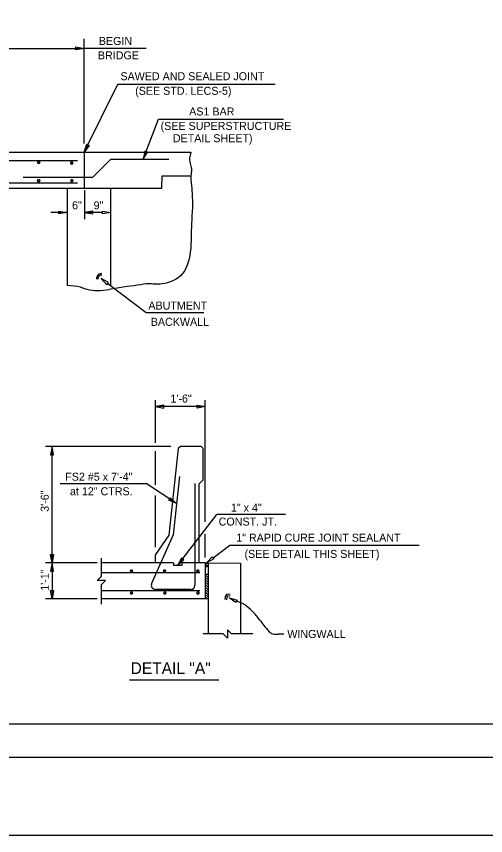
# Model space of a CAD drawing. Extents: x 570 to 2152770, y 726 to 141756.
# Drawn here: x 2151329.5 to 2151386, y 141477.7 to 141576.2 of the extents above; entities that cross this region are included whole.
import ezdxf

# ---------------------------------------------------------------- set-up
doc = ezdxf.new("R2010")
doc.units = 0
for name, color, linetype in [('2', 7, 'Continuous'), ('4', 7, 'Continuous'), ('5', 7, 'Continuous'), ('6', 7, 'Continuous'), ('Default', 7, 'Continuous'), ('PR_Dimensions', 7, 'Continuous'), ('PR_Reinforcing', 7, 'Continuous'), ('SHT_Plot_Shape_Full', 7, 'Continuous'), ('SHT_Plot_Shape_Half', 7, 'Continuous'), ('SHT_Sheet_Border', 7, 'Continuous'), ('T', 7, 'Continuous')]:
    doc.layers.add(name, color=color, linetype=linetype)

# ---------------------------------------------------------------- blocks, each defined once
blk = doc.blocks.new('ARROWHD_7')
at = {"layer": 'Default'}
blk.add_lwpolyline([(0.0261, -0.0045), (0.0261, 0.0043), (-0.0004, -0.0001)], close=True, dxfattribs=at)
blk = doc.blocks.new('DWG01008_2')
at = {"layer": 'Default'}
for p, q in [((-0.0132, 0), (0, 0.0132)), ((0, 0.0132), (0, -0.0132)), ((0, -0.0132), (0.0132, 0))]:
    blk.add_line(p, q, dxfattribs=at)

msp = doc.modelspace()

# ---------------------------------------------------------------- linework, layer by layer
at = {"layer": '2'}
for p, q in [((2151352.573, 141510.47), (2151352.573, 141501.917)), ((2151352.573, 141510.47), (2151356.47, 141510.433)), ((2151356.47, 141510.433), (2151356.47, 141501.917))]:
    msp.add_line(p, q, dxfattribs=at)
at = {"layer": '4'}
for p, q in [((2151348.963, 141524.221), (2151347.864, 141513.803)), ((2151349.239, 141524.47), (2151348.963, 141524.221)), ((2151351.739, 141524.47), (2151349.239, 141524.47)), ((2151351.739, 141524.47), (2151351.989, 141524.22)), ((2151351.989, 141520.47), (2151351.989, 141524.22)), ((2151351.989, 141520.47), (2151351.489, 141519.97)), ((2151351.489, 141510.47), (2151351.489, 141519.97)), ((2151347.864, 141513.803), (2151346.239, 141511.47)), ((2151346.239, 141510.47), (2151346.239, 141511.47)), ((2151348.406, 141510.47), (2151339.728, 141510.47)), ((2151348.406, 141510.47), (2151348.406, 141510.137)), ((2151349.406, 141510.137), (2151348.406, 141510.137)), ((2151352.239, 141510.47), (2151349.406, 141510.47)), ((2151349.406, 141510.47), (2151349.406, 141510.137)), ((2151352.239, 141510.47), (2151352.239, 141506.137)), ((2151352.239, 141506.137), (2151339.728, 141506.137)), ((2151343.119, 141496.411), (2151353.877, 141496.411))]:
    msp.add_line(p, q, dxfattribs=at)
at = {"layer": '5'}
for p, q in [((2151307.894, 141559.876), (2151337.667, 141559.876)), ((2151337.667, 141559.876), (2151350.511, 141559.876)), ((2151337.667, 141559.876), (2151337.667, 141555.543)), ((2151347.02, 141555.543), (2151347.023, 141557.043)), ((2151347.023, 141557.043), (2151350.511, 141557.043)), ((2151307.894, 141555.543), (2151347.02, 141555.543)), ((2151335.599, 141555.543), (2151335.599, 141543.825)), ((2151340.831, 141555.543), (2151340.831, 141543.825))]:
    msp.add_line(p, q, dxfattribs=at)
at = {"layer": '6'}
for p, q in [((2151350.511, 141557.043), (2151350.514, 141556.543)), ((2151342.843, 141543.731), (2151340.679, 141543.375))]:
    msp.add_line(p, q, dxfattribs=at)
msp.add_lwpolyline([(2151337.953, 141560.837), (2151338.252, 141560.69), (2151337.662, 141559.866)], close=True, dxfattribs=at)
for points in [[(2151350.511, 141559.876), (2151350.407, 141559.525), (2151350.353, 141559.218), (2151350.341, 141558.952), (2151350.359, 141558.72), (2151350.399, 141558.519), (2151350.449, 141558.343), (2151350.5, 141558.188), (2151350.541, 141558.049), (2151350.565, 141557.921), (2151350.574, 141557.801), (2151350.571, 141557.684), (2151350.56, 141557.569), (2151350.544, 141557.45), (2151350.529, 141557.326), (2151350.516, 141557.191), (2151350.511, 141557.043)], [(2151350.514, 141556.543), (2151350.604, 141555.519), (2151350.657, 141554.644), (2151350.679, 141553.898), (2151350.677, 141553.259), (2151350.659, 141552.704), (2151350.631, 141552.212), (2151350.6, 141551.761), (2151350.573, 141551.33), (2151350.556, 141550.899), (2151350.546, 141550.467), (2151350.54, 141550.035), (2151350.533, 141549.602), (2151350.523, 141549.17), (2151350.506, 141548.74), (2151350.477, 141548.312), (2151350.434, 141547.887), (2151350.372, 141547.468), (2151350.289, 141547.056), (2151350.184, 141546.658), (2151350.054, 141546.276), (2151349.897, 141545.916), (2151349.712, 141545.58), (2151349.497, 141545.275), (2151349.249, 141545.003), (2151348.968, 141544.768), (2151348.662, 141544.568), (2151348.338, 141544.402), (2151348.007, 141544.268), (2151347.678, 141544.163), (2151347.358, 141544.084), (2151347.057, 141544.03), (2151346.784, 141543.999), (2151346.544, 141543.987), (2151346.331, 141543.99), (2151346.136, 141544.003), (2151345.949, 141544.02), (2151345.759, 141544.036), (2151345.557, 141544.047), (2151345.334, 141544.046), (2151345.08, 141544.028), (2151344.787, 141543.991), (2151344.454, 141543.939), (2151344.082, 141543.879), (2151343.673, 141543.818), (2151343.227, 141543.764), (2151342.843, 141543.731)], [(2151335.599, 141543.868), (2151335.989, 141543.861), (2151336.448, 141543.818), (2151336.829, 141543.751), (2151337.152, 141543.669), (2151337.437, 141543.579), (2151337.707, 141543.488), (2151337.983, 141543.406), (2151338.28, 141543.338), (2151338.599, 141543.287), (2151338.934, 141543.253), (2151339.281, 141543.238), (2151339.634, 141543.241), (2151339.988, 141543.265), (2151340.338, 141543.309), (2151340.679, 141543.375)]]:
    msp.add_lwpolyline(points, dxfattribs=at)
at = {"layer": 'PR_Dimensions'}
for p, q in [((2151337.649, 141560.93), (2151337.649, 141573.518)), ((2151307.75, 141572.376), (2151337.649, 141572.376)), ((2151345.122, 141572.376), (2151337.649, 141572.376)), ((2151337.667, 141559.876), (2151341.696, 141568.08)), ((2151341.696, 141568.08), (2151360.645, 141568.08)), ((2151344.753, 141559.043), (2151346.607, 141563.862)), ((2151346.607, 141563.862), (2151361.65, 141563.862)), ((2151337.688, 141555.325), (2151337.688, 141551.836)), ((2151335.587, 141552.616), (2151333.649, 141552.616)), ((2151339.869, 141552.616), (2151337.73, 141552.616)), ((2151340.483, 141544.064), (2151345.132, 141540.575)), ((2151345.132, 141540.575), (2151352.053, 141540.575)), ((2151346.239, 141524.921), (2151346.239, 141530.063)), ((2151352.239, 141515.391), (2151352.239, 141530.063)), ((2151352.239, 141529.263), (2151346.239, 141529.263)), ((2151348.071, 141524.47), (2151332.976, 141524.47)), ((2151333.776, 141510.47), (2151333.776, 141524.47)), ((2151346.239, 141519.856), (2151346.239, 141523.924)), ((2151334.772, 141520.001), (2151345.108, 141520.001)), ((2151348.767, 141517.593), (2151345.108, 141520.001)), ((2151346.239, 141512.371), (2151346.239, 141518.575)), ((2151348.906, 141510.137), (2151353.623, 141516.3)), ((2151361.878, 141516.3), (2151353.623, 141516.3)), ((2151352.239, 141511.118), (2151352.239, 141513.913)), ((2151353.181, 141511.08), (2151355.186, 141512.584)), ((2151355.186, 141512.584), (2151377.977, 141512.584)), ((2151339.728, 141508.854), (2151339.728, 141511.034)), ((2151339.228, 141510.47), (2151332.976, 141510.47)), ((2151333.776, 141510.47), (2151333.776, 141506.137)), ((2151339.228, 141510.47), (2151334.59, 141510.47)), ((2151352.573, 141509.056), (2151352.239, 141509.056)), ((2151352.573, 141508.7), (2151352.239, 141509.034)), ((2151352.573, 141508.406), (2151352.239, 141508.739)), ((2151352.573, 141508.111), (2151352.239, 141508.444)), ((2151352.573, 141507.816), (2151352.239, 141508.15)), ((2151339.728, 141505.52), (2151339.728, 141507.854)), ((2151352.573, 141507.522), (2151352.239, 141507.855)), ((2151352.573, 141507.227), (2151352.239, 141507.561)), ((2151352.573, 141506.933), (2151352.239, 141507.266)), ((2151339.228, 141506.137), (2151332.976, 141506.137)), ((2151352.573, 141506.638), (2151352.239, 141506.971)), ((2151352.573, 141506.343), (2151352.239, 141506.677)), ((2151352.479, 141506.143), (2151352.239, 141506.382)), ((2151352.573, 141506.143), (2151352.239, 141506.143)), ((2151354.39, 141501.917), (2151351.987, 141501.917)), ((2151357.973, 141501.917), (2151355.39, 141501.917))]:
    msp.add_line(p, q, dxfattribs=at)
for points in [[(2151336.649, 141572.209), (2151336.649, 141572.543), (2151337.649, 141572.376)], [(2151334.602, 141552.45), (2151334.602, 141552.783), (2151335.602, 141552.617)], [(2151338.678, 141552.449), (2151338.678, 141552.782), (2151337.678, 141552.616)], [(2151339.869, 141552.45), (2151339.869, 141552.783), (2151340.869, 141552.616)], [(2151340.383, 141543.931), (2151340.584, 141544.198), (2151339.684, 141544.665)], [(2151347.239, 141529.096), (2151347.239, 141529.43), (2151346.239, 141529.263)], [(2151351.239, 141529.096), (2151351.239, 141529.43), (2151352.239, 141529.263)], [(2151333.609, 141523.47), (2151333.943, 141523.47), (2151333.776, 141524.47)], [(2151347.835, 141518.006), (2151348.019, 141518.285), (2151348.767, 141517.593)], [(2151333.609, 141511.47), (2151333.943, 141511.47), (2151333.776, 141510.47)], [(2151353.081, 141511.213), (2151353.281, 141510.947), (2151352.381, 141510.48)], [(2151333.609, 141509.469), (2151333.943, 141509.469), (2151333.776, 141510.469)], [(2151333.609, 141507.139), (2151333.943, 141507.139), (2151333.776, 141506.139)], [(2151356.074, 141505.99), (2151355.933, 141505.688), (2151355.098, 141506.264)]]:
    msp.add_lwpolyline(points, close=True, dxfattribs=at)
for points in [[(2151355.215, 141506.718), (2151354.782, 141506.669), (2151354.625, 141506.416), (2151354.602, 141506.045)], [(2151355.237, 141506.521), (2151354.9, 141506.482), (2151354.821, 141506.354), (2151354.801, 141506.033)], [(2151361.711, 141501.878), (2151360.996, 141501.878)]]:
    msp.add_lwpolyline(points, dxfattribs=at)
for centre, radius, start, end in [((2151339.967, 141544.576), 0.848, 176.59755, 178.26122), ((2151339.911, 141544.579), 0.793, 153.77604, 176.59755), ((2151340.099, 141544.486), 1.002, 148.98802, 153.77604), ((2151339.982, 141544.557), 0.866, 143.75401, 148.98802), ((2151339.675, 141544.782), 0.484, 95.79435, 143.75401), ((2151339.911, 141544.579), 0.626, 153.77604, 176.59755), ((2151339.967, 141544.576), 0.682, 176.59755, 177.83585), ((2151340.099, 141544.486), 0.835, 148.98802, 153.77604), ((2151339.982, 141544.557), 0.699, 143.75401, 148.98802), ((2151339.675, 141544.782), 0.318, 95.79435, 143.75401), ((2151339.682, 141544.706), 0.561, 78.74108, 95.79435), ((2151339.682, 141544.706), 0.394, 73.86859, 95.79435), ((2151352.406, 141510.644), 0.24, 226.27744, 313.72256), ((2151352.405, 141510.105), 0.0833, 0, 180), ((2151352.405, 141510.105), 0.0833, 180, 0), ((2151354.332, 141500.238), 5.845, 64.82987, 73.38556), ((2151356.136, 141504.076), 1.604, 48.45934, 64.82987), ((2151340.907, 141486.887), 24.569, 45.78007, 48.45934), ((2151355.168, 141501.542), 4.12, 39.23457, 45.78007), ((2151344.832, 141493.102), 17.464, 36.99349, 39.23457), ((2151380.207, 141519.753), 26.827, 216.99349, 218.80165), ((2151374.344, 141515.038), 19.303, 218.80165, 221.75358), ((2151360.7, 141502.859), 1.014, 221.75358, 234.66211), ((2151360.448, 141502.503), 0.578, 234.66211, 260.10442), ((2151360.996, 141505.645), 3.766, 260.10442, 270)]:
    msp.add_arc(centre, radius, start, end, dxfattribs=at)
at = {"layer": 'PR_Reinforcing'}
for p, q in [((2151307.894, 141558.876), (2151336.834, 141558.876)), ((2151340.858, 141559.042), (2151338.68, 141556.864)), ((2151340.858, 141559.042), (2151347.858, 141559.042)), ((2151330.294, 141556.864), (2151338.68, 141556.864)), ((2151307.894, 141556.21), (2151336.834, 141556.21)), ((2151349.11, 141520.848), (2151348.372, 141513.847)), ((2151350.989, 141520.018), (2151350.989, 141507.778)), ((2151348.372, 141513.847), (2151345.775, 141507.98)), ((2151351.583, 141509.252), (2151339.728, 141509.252)), ((2151351.583, 141507.085), (2151339.728, 141507.085)), ((2151350.489, 141507.278), (2151346.233, 141507.278))]:
    msp.add_line(p, q, dxfattribs=at)
for centre in [(2151332.167, 141558.635), (2151336.149, 141558.57), (2151332.17, 141556.458), (2151336.17, 141556.457), (2151343.337, 141509.489), (2151347.328, 141509.487), (2151351.339, 141509.486), (2151343.355, 141506.846), (2151347.356, 141506.844), (2151351.352, 141506.846)]:
    msp.add_circle(centre, 0.124, dxfattribs=at)
for centre, radius, start, end in [((2151332.168, 141558.631), 0.125, 0, 180), ((2151332.168, 141558.631), 0.125, 180, 0), ((2151336.144, 141558.572), 0.125, 0, 180), ((2151336.144, 141558.572), 0.125, 180, 0), ((2151332.168, 141556.455), 0.125, 0, 180), ((2151332.168, 141556.455), 0.125, 180, 0), ((2151336.168, 141556.455), 0.125, 0, 180), ((2151336.168, 141556.455), 0.125, 180, 0), ((2151343.337, 141509.485), 0.125, 0, 180), ((2151343.337, 141509.485), 0.125, 180, 0), ((2151347.337, 141509.485), 0.125, 0, 180), ((2151347.337, 141509.485), 0.125, 180, 0), ((2151351.337, 141509.485), 0.125, 0, 180), ((2151351.337, 141509.485), 0.125, 180, 0), ((2151346.233, 141507.778), 0.5, 156.12911, 270), ((2151350.489, 141507.778), 0.5, 270, 0), ((2151343.357, 141506.844), 0.125, 0, 180), ((2151343.357, 141506.844), 0.125, 180, 0), ((2151347.357, 141506.844), 0.125, 0, 180), ((2151347.357, 141506.844), 0.125, 180, 0), ((2151351.357, 141506.844), 0.125, 0, 180), ((2151351.357, 141506.844), 0.125, 180, 0)]:
    msp.add_arc(centre, radius, start, end, dxfattribs=at)
at = {"layer": 'SHT_Plot_Shape_Full'}
msp.add_lwpolyline([(2151212.548, 141669.654), (2151500.548, 141669.654), (2151500.548, 141477.654), (2151212.548, 141477.654)], close=True, dxfattribs=at)
at = {"layer": 'SHT_Plot_Shape_Half'}
msp.add_lwpolyline([(2151225.648, 141663.054), (2151497.648, 141663.054), (2151497.648, 141487.054), (2151225.648, 141487.054)], close=True, dxfattribs=at)
at = {"layer": 'SHT_Sheet_Border'}
msp.add_lwpolyline([(2151493.248, 141491.054), (2151241.248, 141491.054), (2151241.248, 141659.054), (2151493.248, 141659.054)], close=True, dxfattribs=at)

# ---------------------------------------------------------------- block references
at = {"layer": '6', "xscale": 37.7952, "yscale": 37.7952, "rotation": 68.96374520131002}
msp.add_blockref('ARROWHD_7', (2151344.753, 141559.043), dxfattribs=at)
at = {"layer": 'PR_Dimensions', "xscale": 37.7952}
for name, p, yscale, rotation in [('ARROWHD_7', (2151348.906, 141510.137), 37.7952, 52.57268367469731), ('DWG01008_2', (2151339.728, 141508.354), -37.7952, 89.99999999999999), ('DWG01008_2', (2151354.89, 141501.917), -37.7952, 180)]:
    msp.add_blockref(name, p, dxfattribs=dict(at, yscale=yscale, rotation=rotation))

# ---------------------------------------------------------------- texts
at = {"layer": '4'}
msp.add_text('DETAIL "A"', height=1.4, dxfattribs=at).set_placement((2151343.24, 141497.098))
at = {"layer": 'T'}
for s, height, p in [('BEGIN', 0.9635, (2151339.413, 141572.781)), ('BRIDGE', 0.9635, (2151339.303, 141571.053)), ('SAWED AND SEALED JOINT', 0.96354, (2151342.015, 141568.538)), ('(SEE STD. LECS-5)', 0.96354, (2151343.793, 141566.785)), ('AS1 BAR', 0.9635, (2151350.297, 141564.296)), ('(SEE SUPERSTRUCTURE', 0.96354, (2151346.855, 141562.557)), ('DETAIL SHEET)', 0.96354, (2151348.331, 141561.08)), ('6"', 0.9635, (2151336.19, 141553.007)), ('9"', 0.9635, (2151338.788, 141553.007)), ('ABUTMENT', 0.9635, (2151345.381, 141540.949)), ('BACKWALL', 0.9635, (2151345.671, 141538.988)), ('1\'-6"', 0.9635, (2151348.039, 141529.759)), ('FS2 #5 x 7\'-4"', 0.96354, (2151335.371, 141520.356)), ('at 12" CTRS.', 0.96354, (2151335.94, 141518.603)), ('1" x 4"', 0.9635, (2151355.322, 141516.632)), ('CONST. JT.', 0.9635, (2151353.847, 141514.953)), ('1" RAPID CURE JOINT SEALANT', 0.96354, (2151355.962, 141513.019)), ('(SEE DETAIL THIS SHEET)', 0.96354, (2151356.96, 141511.067)), ('WINGWALL', 0.9635, (2151362.114, 141501.429))]:
    msp.add_text(s, height=height, dxfattribs=at).set_placement(p)
for s, p in [('3\'-6"', (2151333.382, 141516.609)), ('1\'-1"', (2151333.387, 141507.117))]:
    msp.add_text(s, height=0.9635, rotation=90, dxfattribs=at).set_placement(p)

doc.saveas('drawing.dxf')
